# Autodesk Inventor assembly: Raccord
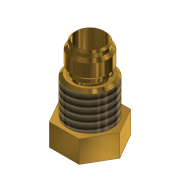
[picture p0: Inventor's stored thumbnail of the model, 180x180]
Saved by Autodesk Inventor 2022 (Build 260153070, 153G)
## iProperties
Created: 2018-06
Part Number: Raccord
Material: Générique
Document SubType Name: Assembly
Designer: Fabian Perrée
Author: Fabian Perrée
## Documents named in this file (3)
- C:\Users\Fabian\Google Drive\01_Giup\01_Clients\07_ENI\Manuscrit\Fichiers_exercice\Chapitre_06\Exercice_de_fin_de_chapitre\Exercice_fin_de_chapitre_solution\Ens_raccord.iam
- C:\Users\Fabian\Google Drive\01_Giup\01_Clients\07_ENI\Manuscrit\Fichiers_exercice\Chapitre_06\Exercice_de_fin_de_chapitre\Composants\Bague.ipt
- C:\Users\Fabian\Google Drive\01_Giup\01_Clients\07_ENI\Manuscrit\Fichiers_exercice\Chapitre_06\Exercice_de_fin_de_chapitre\Composants\Vis_hexa.ipt
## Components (2 placed, 2 different names)
1. Bague:1
2. Vis_hexa:1
